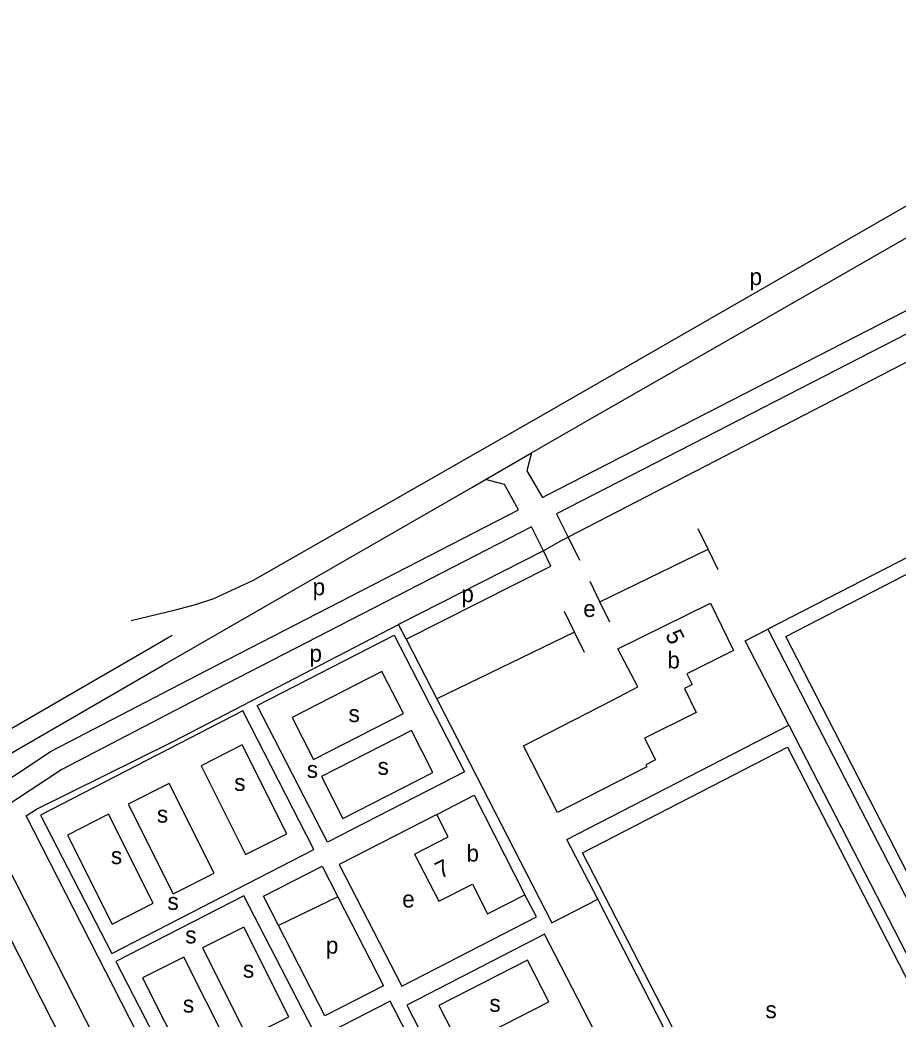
# Model space of a CAD drawing. Extents: x 158848 to 160613, y 385889 to 387762.
# Drawn here: x 159340 to 159549.1, y 387434.6 to 387672.4 of the extents above; entities that cross this region are included whole.
import ezdxf

# ---------------------------------------------------------------- set-up
doc = ezdxf.new("R2010")
doc.units = 0
for name, color, linetype in [('BLT_Basislijn', 7, 'Continuous'), ('BLT_Bebouwing', 7, 'Continuous'), ('BLT_Centroide', 7, 'Continuous'), ('BLT_Huisnummer', 7, 'Continuous')]:
    doc.layers.add(name, color=color, linetype=linetype)

msp = doc.modelspace()

# ---------------------------------------------------------------- linework, layer by layer
at = {"layer": 'BLT_Basislijn'}
for p, q in [((159554.7, 387592.87), (159470.47, 387549.32)), ((159450.86, 387563.03), (159461.81, 387569.37)), ((159573.67, 387556.01), (159518.09, 387527.4)), ((159467.7, 387554.83), (159470.47, 387549.32)), ((159464.61, 387546.09), (159461.77, 387551.78)), ((159503.84, 387546.42), (159501.48, 387551.28)), ((159469.27, 387548.66), (159470.47, 387549.32)), ((159470.47, 387549.32), (159473.22, 387543.85)), ((159469.27, 387548.66), (159464.61, 387546.09)), ((159478.08, 387533.9), (159503.84, 387546.42)), ((159506.2, 387541.56), (159503.84, 387546.42)), ((159464.61, 387546.09), (159430.14, 387528.54)), ((159478.08, 387533.9), (159475.72, 387538.76)), ((159480.44, 387529.04), (159478.08, 387533.9)), ((159472.01, 387526.71), (159469.64, 387531.57)), ((159431.95, 387525.02), (159430.14, 387528.54)), ((159512.69, 387524.62), (159518.09, 387527.4)), ((159518.09, 387527.4), (159609.05, 387350.64)), ((159431.95, 387525.02), (159466.66, 387457.48)), ((159472.01, 387526.71), (159439.27, 387510.79)), ((159474.37, 387521.84), (159472.01, 387526.71)), ((159523.03, 387504.54), (159512.69, 387524.62)), ((159439.2, 387483.29), (159415.95, 387471.4)), ((159324.69, 387479.19), (159381.98, 387366.86)), ((159415.95, 387471.4), (159430.87, 387442.41)), ((159415.67, 387463.71), (159401.53, 387456.84)), ((159462.94, 387458.91), (159460.23, 387464.18)), ((159466.66, 387457.48), (159477.56, 387463.09)), ((159430.87, 387442.41), (159462.94, 387458.91))]:
    msp.add_line(p, q, dxfattribs=at)
for points in [[(159366.46, 387529.48), (159377.34, 387532.08), (159381.76, 387533.29), (159386.12, 387534.68), (159395.43, 387539.01), (159461.28, 387576.64), (159590.7, 387651.01), (159627.31, 387672.45)], [(159461.81, 387569.37), (159474.7, 387576.82), (159507.61, 387595.64), (159543.13, 387616.06), (159577.81, 387635.96), (159601.31, 387649.37), (159609.52, 387653.21), (159619.3, 387656.6), (159623, 387657.86), (159630.59, 387660.91), (159635.17, 387663.17)], [(159464.36, 387558.73), (159465.41, 387559.27), (159609.47, 387633.31), (159615.29, 387637.03), (159620.23, 387641.69), (159624.25, 387648.41), (159626.53, 387651.56), (159629.7, 387654.01), (159634.03, 387656.74), (159637.46, 387659.24), (159635.17, 387663.17)], [(159633.21, 387650.31), (159630.92, 387647.07), (159623.92, 387638.3), (159618.38, 387633.07), (159611.96, 387628.97), (159554.12, 387599.25), (159500, 387571.43), (159467.7, 387554.83)], [(159461.81, 387569.37), (159460.66, 387565.1), (159464.36, 387558.73)], [(159328.58, 387492.57), (159333.29, 387495.3), (159373.93, 387518.77), (159411.13, 387540.18), (159447.6, 387561.14), (159450.86, 387563.03)], [(159458.7, 387555.82), (159455.34, 387561.82), (159450.86, 387563.03)], [(159328.58, 387492.57), (159331.26, 387487.7), (159347.42, 387498.33), (159384.23, 387517.51), (159458.7, 387555.82)], [(159461.77, 387551.78), (159386.53, 387513.07), (159349.96, 387494.01), (159331.67, 387481.98), (159331.4, 387481.81)], [(159431.95, 387525.02), (159466.4, 387542.41), (159464.61, 387546.09)], [(159396.38, 387375.43), (159341.48, 387482.99), (159343.93, 387484.55), (159376.43, 387500.64), (159430.14, 387528.54)], [(159376.24, 387525.86), (159371.44, 387523.1), (159330.78, 387499.63), (159326.31, 387497.03)], [(159477.56, 387463.09), (159470.21, 387477.36), (159523.03, 387504.54)], [(159523.03, 387504.54), (159614.85, 387326.13)], [(159403.53, 387478.66), (159392.91, 387499.83), (159383.09, 387494.9), (159393.71, 387473.73), (159403.53, 387478.66)], [(159386.24, 387469.3), (159375.54, 387490.63), (159365.74, 387485.71), (159376.44, 387464.38), (159386.24, 387469.3)], [(159351.32, 387478.39), (159361.95, 387457.2), (159371.71, 387462.19), (159361.05, 387483.38), (159351.32, 387478.39)], [(159331.4, 387481.81), (159384.31, 387377.84), (159386.48, 387374.37), (159388.21, 387372.6), (159389.47, 387372.33), (159392.17, 387373.2), (159396.38, 387375.43)], [(159401.53, 387456.84), (159397.95, 387463.83), (159411.94, 387471), (159415.67, 387463.71)], [(159415.67, 387463.71), (159426.53, 387442.5), (159412.53, 387435.34), (159401.53, 387456.84)], [(159496.34, 387426.59), (159477.56, 387463.09)], [(159403.96, 387435.14), (159393.26, 387456.47), (159383.45, 387451.55), (159394.15, 387430.22), (159403.96, 387435.14)], [(159389.69, 387428.01), (159378.99, 387449.34), (159369.19, 387444.42), (159379.89, 387423.09), (159389.69, 387428.01)]]:
    msp.add_lwpolyline(points, dxfattribs=at)
for points in [[(159571.19, 387550.83), (159612.89, 387469.8), (159564, 387444.64), (159522.3, 387525.67)], [(159396.49, 387509.22), (159429.06, 387525.98), (159445.81, 387493.43), (159413.24, 387476.67)], [(159426.15, 387517.31), (159404.76, 387506.39), (159409.87, 387496.37), (159431.27, 387507.3)], [(159393.01, 387507.93), (159344.87, 387483.15), (159361.82, 387450.21), (159409.96, 387474.98)], [(159433.17, 387503.28), (159411.77, 387492.35), (159416.89, 387482.34), (159438.28, 387493.27)], [(159522.72, 387499.29), (159564.53, 387418.06), (159515.73, 387392.95), (159473.93, 387474.18)], [(159393.3, 387463.94), (159362.82, 387448.26), (159379.32, 387416.21), (159409.8, 387431.89)], [(159464.89, 387454.79), (159432.09, 387437.9), (159447.84, 387407.28), (159480.65, 387424.17)], [(159460.86, 387448.58), (159439.75, 387437.82), (159444.8, 387427.91), (159465.91, 387438.68)], [(159428.14, 387438.85), (159380.07, 387414.11), (159396.83, 387381.54), (159444.9, 387406.27)]]:
    msp.add_lwpolyline(points, close=True, dxfattribs=at)
at = {"layer": 'BLT_Bebouwing'}
for p, q in [((159439.2, 387483.29), (159448.09, 387487.85)), ((159448.09, 387487.85), (159460.23, 387464.18)), ((159441.94, 387477.96), (159439.2, 387483.29)), ((159433.93, 387473.84), (159441.94, 387477.96)), ((159433.93, 387473.84), (159439.69, 387462.64)), ((159439.69, 387462.64), (159447.71, 387466.71)), ((159447.71, 387466.71), (159451.34, 387459.61)), ((159451.34, 387459.61), (159460.23, 387464.18))]:
    msp.add_line(p, q, dxfattribs=at)
for points in [[(159482.31, 387522.69), (159504.4, 387533.58)], [(159504.4, 387533.58), (159509.89, 387522.34)], [(159459.85, 387499.61), (159481.1, 387510.49), (159487.06, 387513.65), (159482.31, 387522.69)], [(159509.89, 387522.34), (159498.74, 387516.8), (159500.07, 387514.22), (159498.21, 387513.26), (159501.02, 387507.54), (159488.69, 387501.45)], [(159488.69, 387501.45), (159491.33, 387496.31), (159489.01, 387495.14), (159489.26, 387494.63), (159467.97, 387483.74), (159459.85, 387499.61)]]:
    msp.add_lwpolyline(points, dxfattribs=at)

# ---------------------------------------------------------------- texts
at = {"layer": 'BLT_Centroide'}
for s, p in [('p', (159513.7, 387609.31)), ('p', (159409.67, 387535.47)), ('p', (159445.08, 387533.83)), ('e', (159474.1, 387530.3)), ('p', (159408.91, 387519.65)), ('b', (159494.13, 387518.04)), ('s', (159418.22, 387505.29)), ('s', (159408.27, 387491.99)), ('s', (159425.14, 387492.72)), ('s', (159391, 387488.89)), ('s', (159372.59, 387481.34)), ('b', (159446.3, 387472.07)), ('s', (159361.64, 387471.48)), ('s', (159375.1, 387460.57)), ('e', (159431, 387461.14)), ('s', (159379.34, 387452.59)), ('p', (159412.81, 387450.15)), ('s', (159393.07, 387444.42)), ('s', (159451.75, 387436.3)), ('s', (159378.78, 387436.12)), ('s', (159517.49, 387434.78))]:
    msp.add_text(s, height=4, dxfattribs=at).set_placement(p)
at = {"layer": 'BLT_Huisnummer'}
for s, rotation, p in [('5', 296.4032, (159493.53, 387526.05)), ('7', 26.6445, (159440.11, 387467.92))]:
    msp.add_text(s, height=4, rotation=rotation, dxfattribs=at).set_placement(p)

doc.saveas('drawing.dxf')
